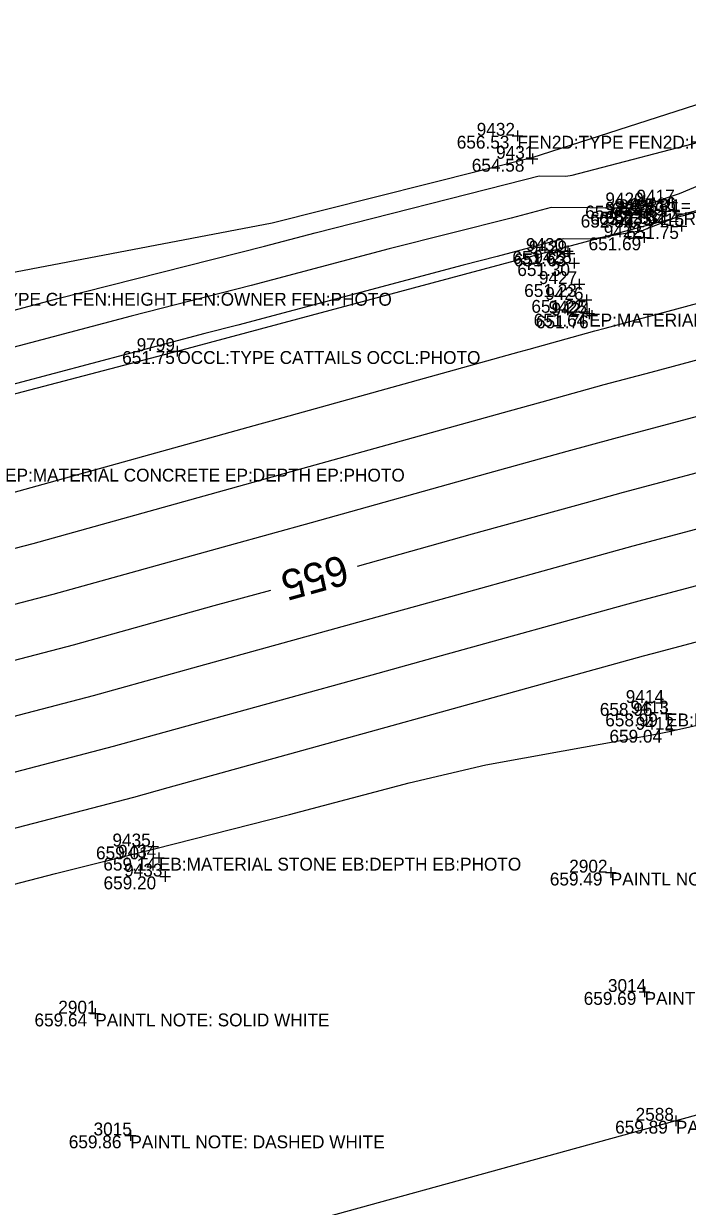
# Model space of a CAD drawing. Extents: x 2129350 to 2137777, y 657588 to 659885.
# Drawn here: x 2134648.3 to 2134710.2, y 659172.4 to 659282.7 of the extents above; entities that cross this region are included whole.
import ezdxf

# ---------------------------------------------------------------- set-up
doc = ezdxf.new("R2010")
doc.units = 0
for name, color, linetype in [('DT_X_Contour_Major', 7, 'Continuous'), ('DT_X_Contour_Minor', 7, 'Continuous'), ('DT_X_TIN_Hull', 7, 'Continuous'), ('PV_X_COP', 7, 'Continuous'), ('SV_X_Occupation_Line', 7, 'Continuous'), ('SV_X_Shot_Marker', 7, 'Continuous'), ('SV_X_Text_Comment', 7, 'Continuous'), ('SV_X_Text_Description', 7, 'Continuous'), ('SV_X_Text_Elevation', 7, 'Continuous'), ('SV_X_Text_Name', 7, 'Continuous')]:
    doc.layers.add(name, color=color, linetype=linetype)

msp = doc.modelspace()

# ---------------------------------------------------------------- linework, layer by layer
at = {"layer": 'DT_X_Contour_Major'}
for points in [[(2134679.4, 659232.16), (2134690.13, 659235.15), (2134700.75, 659238.09), (2134704.22, 659239.05), (2134715.42, 659242.03), (2134728.33, 659245.51), (2134739.79, 659248.55), (2134751.61, 659251.73), (2134753.2, 659252.15), (2134765.87, 659255.64), (2134775.91, 659258.34)], [(2134574.74, 659203.94), (2134583.43, 659206.22), (2134594.69, 659209.19), (2134606.99, 659212.42), (2134607.2, 659212.48), (2134620.3, 659216.13), (2134631.33, 659218.99), (2134642.28, 659222.05), (2134652.91, 659224.81), (2134666.05, 659228.47), (2134671.31, 659229.92)]]:
    msp.add_lwpolyline(points, dxfattribs=at)
at = {"layer": 'DT_X_Contour_Minor'}
for points in [[(2134530.26, 659226.88), (2134550.44, 659231.76), (2134552.34, 659232.21), (2134565.74, 659235.62), (2134570.57, 659236.91), (2134589.05, 659241.63), (2134594.88, 659243.19), (2134598.56, 659243.89), (2134612.92, 659247.41), (2134613.67, 659247.6), (2134613.81, 659247.69), (2134613.89, 659247.61), (2134616.67, 659248.47), (2134635.84, 659253.15), (2134639.67, 659254.05), (2134646.44, 659255.77), (2134651.45, 659257.1), (2134670.72, 659261.99), (2134675.46, 659263.25), (2134695.01, 659268.2), (2134696.33, 659268.55), (2134698.84, 659268.53), (2134699.42, 659268.63), (2134712.76, 659272.09)], [(2134720.3, 659271.44), (2134709.4, 659266.88), (2134706.53, 659265.91), (2134706.26, 659265.84), (2134704.63, 659265.55), (2134697.46, 659265.61), (2134693.72, 659264.62), (2134682.37, 659261.74), (2134669.48, 659258.31), (2134658.31, 659255.48), (2134645.24, 659252)], [(2134720.39, 659267.75), (2134709.21, 659264.82), (2134709.25, 659264.65), (2134709.04, 659264.63), (2134706.06, 659263.47), (2134706.05, 659263.46), (2134706.03, 659263.46), (2134706.03, 659263.46), (2134701.26, 659262.65), (2134698.59, 659262.67), (2134692.42, 659261.03), (2134689.27, 659260.23), (2134668.23, 659254.64), (2134665.16, 659253.86), (2134644.05, 659248.24)], [(2134532.3, 659208.65), (2134554.88, 659214.07), (2134555.76, 659214.28), (2134557.64, 659214.77), (2134579.94, 659220.64), (2134581.82, 659221.13), (2134603.07, 659226.72), (2134603.11, 659226.73), (2134625.76, 659233.05), (2134627.18, 659233.41), (2134646.25, 659238.74), (2134647.28, 659239.01), (2134670.34, 659245.42), (2134671.35, 659245.7), (2134694.47, 659252.14), (2134695.4, 659252.39), (2134701.53, 659254.1), (2134702.5, 659254.36), (2134725.66, 659260.59)], [(2134536.62, 659204.6), (2134556.17, 659209.29), (2134556.93, 659209.47), (2134561.87, 659210.77), (2134581.1, 659215.83), (2134586.11, 659217.15), (2134604.38, 659221.95), (2134604.47, 659221.98), (2134623.94, 659227.41), (2134628.56, 659228.61), (2134644.93, 659233.18), (2134649.15, 659234.27), (2134668.91, 659239.77), (2134673.23, 659240.97), (2134693.02, 659246.47), (2134697.18, 659247.63), (2134702.42, 659249.08), (2134706.8, 659250.25), (2134726.55, 659255.56)], [(2134540.94, 659200.55), (2134557.46, 659204.52), (2134558.1, 659204.67), (2134566.09, 659206.78), (2134582.27, 659211.03), (2134590.4, 659213.17), (2134605.68, 659217.19), (2134605.83, 659217.23), (2134622.12, 659221.77), (2134629.94, 659223.8), (2134643.6, 659227.61), (2134651.03, 659229.54), (2134667.48, 659234.12), (2134675.11, 659236.23), (2134691.57, 659240.81), (2134698.96, 659242.86), (2134703.32, 659244.07), (2134711.11, 659246.14)], [(2134535.8, 659188.83), (2134549.58, 659192.45), (2134560.03, 659194.96), (2134560.44, 659195.06), (2134574.55, 659198.78), (2134584.6, 659201.42), (2134598.99, 659205.21), (2134608.3, 659207.66), (2134608.56, 659207.73), (2134618.48, 659210.5), (2134632.71, 659214.19), (2134640.95, 659216.49), (2134654.78, 659220.08), (2134664.62, 659222.81), (2134678.88, 659226.76), (2134688.68, 659229.49), (2134702.53, 659233.32), (2134705.11, 659234.04), (2134719.72, 659237.92)], [(2134537.1, 659183.99), (2134553.9, 659188.4), (2134561.32, 659190.19), (2134561.6, 659190.26), (2134578.77, 659194.78), (2134585.76, 659196.62), (2134603.28, 659201.23), (2134609.6, 659202.89), (2134609.93, 659202.98), (2134616.66, 659204.86), (2134634.09, 659209.38), (2134639.63, 659210.93), (2134656.66, 659215.35), (2134663.19, 659217.16), (2134680.76, 659222.02), (2134687.24, 659223.83), (2134704.31, 659228.55), (2134706.01, 659229.02), (2134724.03, 659233.81)], [(2134538.41, 659179.15), (2134558.22, 659184.36), (2134562.6, 659185.41), (2134562.77, 659185.45), (2134583, 659190.78), (2134586.92, 659191.81), (2134607.57, 659197.25), (2134610.91, 659198.13), (2134611.29, 659198.23), (2134614.85, 659199.22), (2134635.48, 659204.58), (2134638.3, 659205.36), (2134658.54, 659210.61), (2134661.75, 659211.51), (2134682.64, 659217.29), (2134685.79, 659218.16), (2134706.09, 659223.78), (2134706.91, 659224.01), (2134728.34, 659229.7)], [(2134539.71, 659174.31), (2134562.54, 659180.31), (2134563.89, 659180.63), (2134563.94, 659180.65), (2134587.22, 659186.78), (2134588.09, 659187.01), (2134611.86, 659193.27), (2134612.22, 659193.36), (2134612.66, 659193.48), (2134613.03, 659193.58), (2134636.86, 659199.77), (2134636.98, 659199.8), (2134651.24, 659203.5), (2134660.47, 659205.79), (2134673.07, 659208.98), (2134684.22, 659211.95), (2134691.37, 659213.63), (2134698.58, 659214.92), (2134707.38, 659216.52), (2134708.61, 659216.76), (2134708.88, 659216.82), (2134732.14, 659222.06)]]:
    msp.add_lwpolyline(points, dxfattribs=at)
at = {"layer": 'DT_X_TIN_Hull'}
msp.add_lwpolyline([(2135530.59, 659503.78), (2135475.39, 659489.05), (2135416.67, 659473.77), (2135375.74, 659461.35), (2135332.28, 659448.99), (2135282.8, 659433.85), (2135234.45, 659419.66), (2135187.99, 659405.62), (2135140.1, 659391.95), (2135093.39, 659377.69), (2135039.16, 659363.4), (2134946.54, 659338.8), (2134928.12, 659333.86), (2134885.43, 659322.6), (2134839.28, 659310.17), (2134788.72, 659297.4), (2134742.32, 659285.27), (2134695.66, 659270.22), (2134671.45, 659264.13), (2134637.39, 659257.64), (2134592.77, 659246.33), (2134552.01, 659235.92), (2134498.13, 659222.44), (2134448.36, 659209.51)], dxfattribs=at)
at = {"layer": 'PV_X_COP'}
msp.add_lwpolyline([(2135046.23, 659276.72), (2134998.09, 659262.4), (2134950.01, 659248.29), (2134901.68, 659235.27), (2134853.4, 659222.06), (2134806.14, 659207.81), (2134757.33, 659193.63), (2134709.1, 659180.43), (2134661.25, 659167.25), (2134613.17, 659153.43), (2134564.8, 659140.1), (2134516.96, 659126.54), (2134468.46, 659112.97), (2134420.69, 659099.3), (2134372.8, 659086.61), (2134323.79, 659072.7)], dxfattribs=at)
at = {"layer": 'SV_X_Occupation_Line'}
msp.add_lwpolyline([(2134406.75, 659176.4), (2134469.4, 659192.65), (2134470.91, 659203.28), (2134565.45, 659226.72), (2134662.6, 659252.21), (2134757.72, 659277.68), (2134838.71, 659299.01), (2134949.99, 659326.74)], dxfattribs=at)
at = {"layer": 'SV_X_Shot_Marker'}
for p, q in [((2134694.32, 659272.79), (2134694.32, 659271.79)), ((2134693.82, 659272.29), (2134694.82, 659272.29)), ((2134694.32, 659272.29), (2134694.32, 659272.29)), ((2134695.71, 659270.64), (2134695.71, 659269.64)), ((2134695.21, 659270.14), (2134696.21, 659270.14)), ((2134695.71, 659270.14), (2134695.71, 659270.14)), ((2134705.9, 659265.79), (2134706.9, 659265.79)), ((2134706.4, 659266.29), (2134706.4, 659265.29)), ((2134706.4, 659265.79), (2134706.4, 659265.79)), ((2134708.25, 659266.06), (2134709.25, 659266.06)), ((2134708.75, 659266.56), (2134708.75, 659265.56)), ((2134708.75, 659266.06), (2134708.75, 659266.06)), ((2134708.92, 659265.85), (2134708.92, 659264.85)), ((2134705.34, 659264.93), (2134706.34, 659264.93)), ((2134705.84, 659265.43), (2134705.84, 659264.43)), ((2134705.84, 659264.93), (2134705.84, 659264.93)), ((2134706.24, 659265.2), (2134707.24, 659265.2)), ((2134706.74, 659265.7), (2134706.74, 659264.7)), ((2134706.74, 659265.2), (2134706.74, 659265.2)), ((2134707.66, 659265.26), (2134708.66, 659265.26)), ((2134708.16, 659265.76), (2134708.16, 659264.76)), ((2134708.16, 659265.26), (2134708.16, 659265.26)), ((2134708.42, 659265.35), (2134709.42, 659265.35)), ((2134708.92, 659265.35), (2134708.92, 659265.35)), ((2134709.12, 659263.87), (2134710.12, 659263.87)), ((2134709.62, 659264.37), (2134709.62, 659263.37)), ((2134709.62, 659263.87), (2134709.62, 659263.87)), ((2134705.64, 659262.81), (2134706.64, 659262.81)), ((2134706.14, 659263.31), (2134706.14, 659262.31)), ((2134706.14, 659262.81), (2134706.14, 659262.81)), ((2134698.53, 659261.54), (2134699.53, 659261.54)), ((2134699.03, 659262.04), (2134699.03, 659261.04)), ((2134699.03, 659261.54), (2134699.03, 659261.54)), ((2134699.17, 659261.81), (2134699.17, 659260.81)), ((2134698.67, 659261.31), (2134699.67, 659261.31)), ((2134699.1, 659260.41), (2134700.1, 659260.41)), ((2134699.17, 659261.31), (2134699.17, 659261.31)), ((2134699.6, 659260.91), (2134699.6, 659259.91)), ((2134699.6, 659260.41), (2134699.6, 659260.41)), ((2134699.59, 659258.46), (2134700.59, 659258.46)), ((2134700.09, 659258.96), (2134700.09, 659257.96)), ((2134700.09, 659258.46), (2134700.09, 659258.46)), ((2134700.26, 659256.98), (2134701.26, 659256.98)), ((2134700.76, 659257.48), (2134700.76, 659256.48)), ((2134700.76, 659256.98), (2134700.76, 659256.98)), ((2134701.01, 659256.2), (2134701.01, 659255.2)), ((2134701.27, 659256.03), (2134701.27, 659255.03)), ((2134700.51, 659255.7), (2134701.51, 659255.7)), ((2134700.77, 659255.53), (2134701.77, 659255.53)), ((2134701.01, 659255.7), (2134701.01, 659255.7)), ((2134701.27, 659255.53), (2134701.27, 659255.53)), ((2134662.6, 659252.71), (2134662.6, 659251.71)), ((2134662.1, 659252.21), (2134663.1, 659252.21)), ((2134662.6, 659252.21), (2134662.6, 659252.21)), ((2134707.74, 659219.89), (2134707.74, 659218.89)), ((2134707.24, 659219.39), (2134708.24, 659219.39)), ((2134707.68, 659218.41), (2134708.68, 659218.41)), ((2134707.74, 659219.39), (2134707.74, 659219.39)), ((2134708.18, 659218.91), (2134708.18, 659217.91)), ((2134708.18, 659218.41), (2134708.18, 659218.41)), ((2134708.66, 659217.39), (2134708.66, 659216.39)), ((2134708.16, 659216.89), (2134709.16, 659216.89)), ((2134708.66, 659216.89), (2134708.66, 659216.89)), ((2134660.36, 659206.51), (2134660.36, 659205.51)), ((2134659.86, 659206.01), (2134660.86, 659206.01)), ((2134660.36, 659206.01), (2134660.36, 659206.01)), ((2134660.88, 659205.46), (2134660.88, 659204.46)), ((2134660.38, 659204.96), (2134661.38, 659204.96)), ((2134660.88, 659204.96), (2134660.88, 659204.96)), ((2134703.02, 659204.07), (2134703.02, 659203.07)), ((2134660.96, 659203.21), (2134661.96, 659203.21)), ((2134661.46, 659203.71), (2134661.46, 659202.71)), ((2134661.46, 659203.21), (2134661.46, 659203.21)), ((2134702.52, 659203.57), (2134703.52, 659203.57)), ((2134703.02, 659203.57), (2134703.02, 659203.57)), ((2134705.68, 659192.44), (2134706.68, 659192.44)), ((2134706.18, 659192.94), (2134706.18, 659191.94)), ((2134706.18, 659192.44), (2134706.18, 659192.44)), ((2134654.95, 659190.92), (2134654.95, 659189.92)), ((2134654.45, 659190.42), (2134655.45, 659190.42)), ((2134654.95, 659190.42), (2134654.95, 659190.42)), ((2134709.1, 659180.93), (2134709.1, 659179.93)), ((2134708.6, 659180.43), (2134709.6, 659180.43)), ((2134709.1, 659180.43), (2134709.1, 659180.43)), ((2134657.72, 659179.06), (2134658.72, 659179.06)), ((2134658.22, 659179.56), (2134658.22, 659178.56)), ((2134658.22, 659179.06), (2134658.22, 659179.06))]:
    msp.add_line(p, q, dxfattribs=at)

# ---------------------------------------------------------------- texts
at = {"layer": 'DT_X_Contour_Major'}
msp.add_text('655', height=2.8, rotation=195.4892, dxfattribs=at).set_placement((2134678.07, 659233.25))
at = {"layer": 'SV_X_Text_Comment'}
for s, p in [('FEN2D:TYPE FEN2D:HEIGHT FEN2D:OWNER FEN2D:PHOTO', (2134694.32, 659271.09)), ('14 RCP PIO:PHOTO', (2134707.58, 659263.96)), ('FEN:TYPE TYPE CL FEN:HEIGHT FEN:OWNER FEN:PHOTO', (2134637.4, 659256.44)), ('EP:MATERIAL CONCRETE EP:DEPTH EP:PHOTO', (2134701.01, 659254.5)), ('OCCL:TYPE CATTAILS OCCL:PHOTO', (2134662.6, 659251.01)), ('EP:MATERIAL CONCRETE EP:DEPTH EP:PHOTO', (2134646.54, 659240.04)), ('EB:MATERIAL STONE EB:DEPTH EB:PHOTO', (2134708.18, 659217.21)), ('EB:MATERIAL STONE EB:DEPTH EB:PHOTO', (2134660.88, 659203.76)), ('PAINTL NOTE: SOLID WHITE', (2134703.02, 659202.37)), ('PAINTL NOTE: DASHED WHITE', (2134706.18, 659191.24)), ('PAINTL NOTE: SOLID WHITE', (2134654.95, 659189.23)), ('PAINTL NOTE: DASHED WHITE', (2134709.1, 659179.23)), ('PAINTL NOTE: DASHED WHITE', (2134658.22, 659177.86))]:
    msp.add_text(s, height=1.2, dxfattribs=at).set_placement(p)
at = {"layer": 'SV_X_Text_Description'}
msp.add_text('P1= PIO:P1', height=1.2, dxfattribs=at).set_placement((2134707.58, 659265.16))
at = {"layer": 'SV_X_Text_Elevation'}
for s, p in [('656.53', (2134688.66, 659271.09)), ('654.58', (2134690.06, 659268.94)), ('653.02', (2134700.64, 659264.58)), ('652.89', (2134703.12, 659264.86)), ('652.83', (2134700.22, 659263.73)), ('652.83', (2134701.11, 659264)), ('652.35', (2134701.94, 659263.96)), ('652.83', (2134702.54, 659264.06)), ('652.82', (2134703.31, 659264.15)), ('651.75', (2134704.47, 659262.67)), ('651.69', (2134700.95, 659261.61)), ('651.65', (2134693.84, 659260.34)), ('651.63', (2134693.98, 659260.11)), ('651.30', (2134694.31, 659259.21)), ('651.23', (2134694.95, 659257.26)), ('651.22', (2134695.62, 659255.78)), ('651.64', (2134695.83, 659254.5)), ('651.76', (2134696.05, 659254.33)), ('651.75', (2134657.46, 659251.01)), ('658.96', (2134702, 659218.19)), ('658.99', (2134702.51, 659217.21)), ('659.04', (2134702.9, 659215.69)), ('659.01', (2134655.02, 659204.81)), ('659.14', (2134655.7, 659203.76)), ('659.20', (2134655.72, 659202.01)), ('659.49', (2134697.34, 659202.37)), ('659.69', (2134700.5, 659191.24)), ('659.64', (2134649.28, 659189.23)), ('659.89', (2134703.43, 659179.23)), ('659.86', (2134652.48, 659177.86))]:
    msp.add_text(s, height=1.2, dxfattribs=at).set_placement(p)
at = {"layer": 'SV_X_Text_Name'}
for s, p in [('9432', (2134690.52, 659272.29)), ('9431', (2134692.33, 659270.14)), ('9420', (2134702.52, 659265.79)), ('9417', (2134705.42, 659266.06)), ('9421', (2134702.5, 659264.93)), ('9419', (2134703.4, 659265.2)), ('9423', (2134703.8, 659265.16)), ('9418', (2134704.82, 659265.26)), ('9416', (2134705.52, 659265.35)), ('9415', (2134706.3, 659263.87)), ('9422', (2134702.37, 659262.81)), ('9430', (2134695.11, 659261.54)), ('9429', (2134695.38, 659261.31)), ('9428', (2134695.81, 659260.41)), ('9427', (2134696.32, 659258.46)), ('9426', (2134696.91, 659256.98)), ('9425', (2134697.23, 659255.7)), ('9424', (2134697.5, 659255.53)), ('9799', (2134658.81, 659252.21)), ('9414', (2134704.42, 659219.39)), ('9413', (2134704.86, 659218.41)), ('9412', (2134705.35, 659216.89)), ('9435', (2134656.55, 659206.01)), ('9434', (2134657.07, 659204.96)), ('9433', (2134657.64, 659203.21)), ('2902', (2134699.15, 659203.57)), ('3014', (2134702.76, 659192.44)), ('2901', (2134651.5, 659190.42)), ('2588', (2134705.34, 659180.43)), ('3015', (2134654.79, 659179.06))]:
    msp.add_text(s, height=1.2, dxfattribs=at).set_placement(p)

doc.saveas('drawing.dxf')
